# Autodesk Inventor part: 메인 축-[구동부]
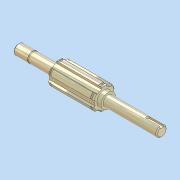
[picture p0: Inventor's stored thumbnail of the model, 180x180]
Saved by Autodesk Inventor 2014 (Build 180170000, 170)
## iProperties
Created: 2012-05
Part Number: 메인 축-[구동부]
Document SubType Name: 모델링
Designer: SeoGD™
Mass: 168.566 g
Surface Area: 72.5104 cm^2
Volume: 21.4461 cm^3
Density: 7.86 g/cm^3
Material: 강철, 연강
Appearance: 강철
변환 표준: STEP AP214IS
파일 이름: C:\Users\SeoGD\Desktop\?쒗뿕\硫붿씤 異?.stp
전처리기: Build: 253, Release: 2010 SP1 - Date: Wed 07/29/2009
전송 단위: 밀리미터
불확실성: 0.01
Author: SeoGD™
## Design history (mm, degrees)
sketch "스케치1"
  geometry: L1 (-69.5, 0)-(69.5, 0); L2 (69.5, 0)-(69.5, 5); L3 (69.5, 5)-(55.5, 5); L4 (55.5, 5)-(55.5, 4.8); L5 (55.5, 4.8)-(54.35, 4.8); L6 (54.35, 4.8)-(54.35, 5); L7 (54.35, 5)-(30.5, 5); L8 (30.5, 5)-(30.5, 9); L9 (30.5, 9)-(-13.5, 9); L10 (-13.5, 9)-(-13.5, 7); L11 (-13.5, 7)-(-17.5, 7); L12 (-17.5, 7)-(-17.5, 5); L13 (-17.5, 5)-(-69.5, 5); L14 (-69.5, 5)-(-69.5, 0); 2 further points
  constraints: 28 end point, 9 parallel, 4 collinear, 2 perpendicular, 1 coincident, 1 horizontal, 1 midpoint
  dimensions: "d2" = 1.15 distance between parallel lines of L6 L4; "d3" = 10 diameter of L3 L1; "d4" = 9.6 diameter of L5 L1; "d6" = 44 distance between parallel lines of L10 L8; "d7" = 4 distance between parallel lines of L12 L10; "d8" = 14 diameter of L11 L1; "d9" = 18 diameter of L9 L1; "d33" = 52 distance from line of L12.end L14; "d37" = 39 distance between parallel lines of L8 L2; "d38" = 14 distance between parallel lines of L2 L4
revolve "회전1" sketch "스케치1" stored, may be unused: angle "d10" = 90 deg
sketch "스케치2"
  geometry: L1 (2.5, 10.712)-(2.5, 8.646); L2 (-2.5, 10.712)-(-2.5, 8.646); A1 r 9 centre (0, 0) between (2.5, 8.646) and (-2.5, 8.646) reference; A2 r 11 centre (0, 0) between (2.5, 10.712) and (-2.5, 10.712); 1 further point
  constraints: 4 end point, 4 point on circle, 2 parallel, 1 centre point, 1 coincident, 1 vertical
  dimensions: "d11" = 22 diameter of A2; "d12" = 5 distance between parallel lines of L1 L2
extrude "돌출1" join sketch "스케치2" stored distance "d13" = 10; taper "d14" = 0 deg
chamfer "모따기1" distance "d15" = 1; stored, may be unused: second distance "d16" = 2, angle "d17" = 45 deg
node "작업 평면1"
node "작업 평면2"
sketch "스케치3"
  geometry: L1 (2.5, 10.712)-(2.5, 10.198); L2 (-2.5, 10.712)-(-2.5, 10.198); A1 r 11 centre (0, 0) between (2.5, 10.712) and (-2.5, 10.712) reference; A2 r 10.5 centre (0, 0) between (2.5, 10.198) and (-2.5, 10.198); 1 further point
  constraints: 4 end point, 2 point on circle, 1 centre point, 1 coincident, 1 parallel, 1 vertical
  dimensions: "d19" = 21 diameter of A2
extrude "돌출2" cut sketch "스케치3" distance "d20" = 1.35; taper "d21" = 0 deg
node "작업 평면3"
sketch "스케치4"
  geometry: L1 (-26, -5)-(-26, 5) reference; L2 (-26, 1.5)-(-12.5, 1.5); L3 (-12.5, -1.5)-(-26, -1.5); A1 r 1.5 centre (-12.5, 0) between (-12.5, -1.5) and (-12.5, 1.5); 2 further points
  constraints: 4 end point, 2 perpendicular, 2 point on circle, 2 point on line, 2 tangent, 1 centre point, 1 horizontal alignment, 1 midpoint
  dimensions: "d25" = 3 distance between parallel lines of L3 L2; "d26" = 15 dimension on A1 L1
extrude "돌출3" cut sketch "스케치4" distance "d27" = 1.8; taper "d28" = 0 deg
chamfer "모따기2" distance "d29" = 1; stored, may be unused: second distance "d30" = 2, angle "d31" = 45 deg
node "솔리드1"
node "솔리드 본체"
node "곡면 본체"
mirror "대칭1"
pattern_circular "원형 패턴1" dims "d23" = 360 deg
node "솔리드2"
other parameters: "d18" = -1.65
